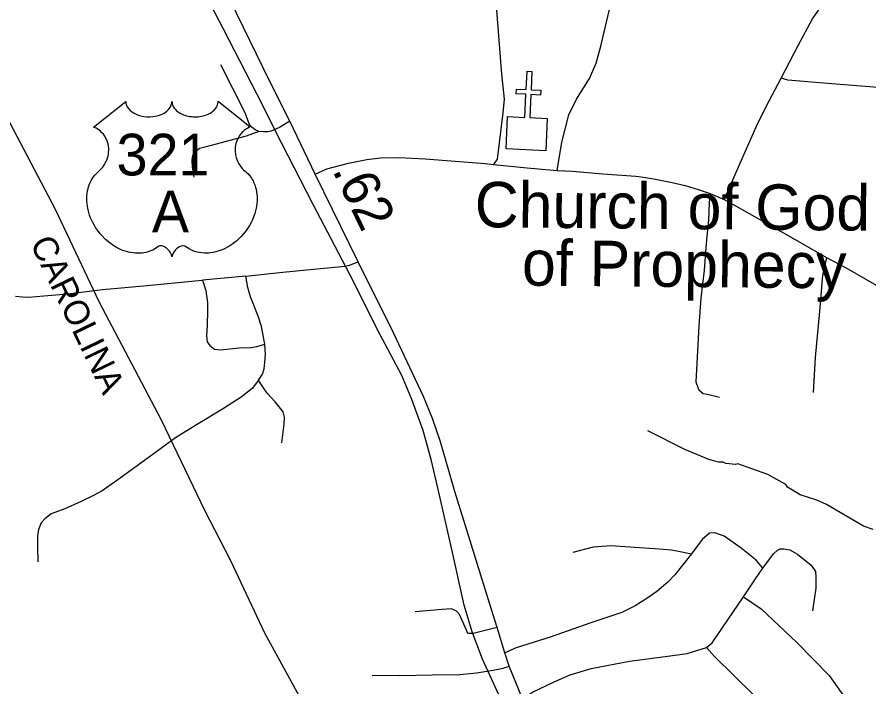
# Model space of a CAD drawing. Extents: x 1159738 to 1321356, y 736314 to 882035.
# Drawn here: x 1266042 to 1268853, y 761438 to 763648 of the extents above; entities that cross this region are included whole.
import ezdxf

# ---------------------------------------------------------------- set-up
doc = ezdxf.new("R2010")
doc.units = 0
for name, color, linetype in [('Exist Cultural Church CELL', 7, 'Continuous'), ('Exist Cultural Church Label', 7, 'Continuous'), ('Exist Hydrographic Misc Water Feature', 7, 'Continuous'), ('Exist Railroad Mainline', 7, 'Continuous'), ('Exist Railroad Mainline Label', 7, 'Continuous'), ('Exist Road Non-System Type 51', 7, 'Continuous'), ('Exist Road Primary US Attributed', 7, 'Continuous'), ('Exist Road Primary US Mileage Hundredths English Label', 7, 'Continuous'), ('Exist Road Primary US Shield CELL', 7, 'Continuous'), ('Exist Road Primary US Shield Number Label', 7, 'Continuous'), ('Exist Utilities Electrical Transmission Line', 7, 'Continuous')]:
    doc.layers.add(name, color=color, linetype=linetype)

msp = doc.modelspace()

# ---------------------------------------------------------------- linework, layer by layer
at = {"layer": 'Exist Cultural Church CELL'}
msp.add_lwpolyline([(1267660.9, 763319.4), (1267717.8, 763316.8), (1267721.4, 763392.9), (1267689.4, 763394.4), (1267690.2, 763410.3), (1267722.1, 763408.8), (1267725, 763468.9), (1267741, 763468.2), (1267738.2, 763408.1), (1267770.1, 763406.6), (1267769.4, 763390.6), (1267737.4, 763392.1), (1267733.8, 763316.1), (1267791.4, 763313.2), (1267786.4, 763206.9), (1267655.9, 763213)], close=True, dxfattribs=at)
at = {"layer": 'Exist Hydrographic Misc Water Feature'}
msp.add_lwpolyline([(1268866.3, 761957.4), (1268834.6, 761968.4), (1268712.6, 762039.8), (1268681, 762054.7), (1268625.5, 762072.3), (1268584.7, 762097.5), (1268578.4, 762105.7), (1268519.2, 762139.4), (1268420.2, 762174.2), (1268412.2, 762172.4), (1268380.2, 762175.4), (1268372.3, 762179.6), (1268356.4, 762180), (1268324.6, 762188.9), (1268245.5, 762221.2), (1268123.2, 762282.7)], dxfattribs=at)
at = {"layer": 'Exist Railroad Mainline'}
msp.add_lwpolyline([(1267632.3, 761412.3), (1267577.6, 761530.2), (1267544.4, 761620), (1267518, 761708.5), (1267474.8, 761901.5), (1267436.6, 762071.1), (1267410.2, 762184.1), (1267382, 762284.6), (1267345, 762386.7), (1267311.8, 762465.8), (1267239.1, 762602.1), (1267140, 762798.6), (1267019.6, 763029.2), (1266916.1, 763231.1), (1266834.7, 763392.2), (1266722.5, 763609.6), (1266667.4, 763716.8), (1266561.4, 763921.8), (1266492.4, 764059.9), (1266431, 764179.4), (1266408.5, 764222.6)], dxfattribs=at)
at = {"layer": 'Exist Road Non-System Type 51'}
for points in [[(1267824.7, 763141.4), (1267839.3, 763234.8), (1267863, 763325.7), (1267887.9, 763376.8), (1267931.5, 763445.4), (1267952.7, 763495.2), (1267968.9, 763551.3), (1268008.6, 763725.3), (1268029.8, 763852.5), (1268064.5, 764031.3), (1268078.2, 764066.2), (1268125.6, 764177.1), (1268150.4, 764204), (1268191.5, 764243.9), (1268225.1, 764295), (1268289.9, 764410.9)], [(1268563.8, 763446.1), (1268619.3, 763553.9), (1268666.8, 763642.2), (1268689.7, 763674.4), (1268713.5, 763702.3), (1268772.5, 763759.3), (1268836.7, 763812.6), (1268924.2, 763880.5), (1269025.3, 763956.6), (1269136.5, 764039.4), (1269295.8, 764161.1), (1269340.5, 764199.1), (1269364.1, 764225.4), (1269391.9, 764247.8), (1269429.9, 764278.4), (1269452.3, 764294), (1269510.6, 764327.3)], [(1267618, 763758.3), (1267626.7, 763642.4), (1267640.4, 763459.7), (1267649.1, 763377.4), (1267645.3, 763331.4), (1267626.7, 763179.4), (1267614.2, 763161.2)], [(1266942, 763304.8), (1266908.1, 763283.6), (1266893.4, 763277.2), (1266880.6, 763271.5), (1266869.7, 763269.5), (1266855.6, 763269.5), (1266840.3, 763270.8), (1266828.1, 763275.3), (1266817.9, 763283.6), (1266809.6, 763293.9), (1266793.6, 763333.6), (1266714.9, 763489.8)], [(1268375.3, 763045.7), (1268456.3, 763230.2), (1268486.2, 763297.9), (1268523.7, 763371.2), (1268563.8, 763446.1)], [(1269869.3, 763313.1), (1269805.5, 763337.6), (1269739.7, 763351.2), (1269587.8, 763361.3), (1269350.3, 763379.7), (1268882.1, 763415), (1268703.1, 763429.9), (1268585.5, 763439.4), (1268563.8, 763446.1)], [(1266840.3, 763270.8), (1266798.1, 763254.8), (1266662.4, 763218.3), (1266644.7, 763214.1), (1266631.3, 763203.2), (1266621.7, 763191.6), (1266619.1, 763176.3), (1266619.8, 763152.6), (1266626, 763120.2)], [(1267025.9, 763129.5), (1267064.3, 763147.4), (1267135.9, 763166), (1267196.7, 763178.4), (1267241.4, 763183.6), (1267303, 763184.3), (1267388.8, 763179.8), (1267586.4, 763164.5), (1267614.2, 763161.2), (1267725, 763150.3), (1267811.9, 763142.5), (1267824.7, 763141.4)], [(1267824.7, 763141.4), (1267875.1, 763139.1), (1267974.8, 763131), (1268083.4, 763122.8), (1268109.1, 763119.4), (1268149.2, 763112.6), (1268204.1, 763101.8), (1268246.9, 763092.3), (1268289.9, 763079.4), (1268328.6, 763065.8)], [(1268328.6, 763065.8), (1268325.9, 763036.1), (1268323.2, 762978.4), (1268317.8, 762924.8), (1268313.7, 762872.5), (1268309.6, 762813.4), (1268298.8, 762720.1), (1268292, 762629.8), (1268285.2, 762505.2), (1268281.8, 762444.8), (1268287.9, 762425.8), (1268292, 762418.3), (1268306.3, 762406.1), (1268320.4, 762404.3), (1268360.4, 762394.2)], [(1268328.6, 763065.8), (1268375.3, 763045.7)], [(1268375.3, 763045.7), (1268414.7, 763023.9), (1268493.4, 762979.8), (1268586.3, 762927.5), (1268712.5, 762854.9)], [(1268712.5, 762854.9), (1268699.6, 762795.6), (1268689.9, 762677.5), (1268675.8, 762524.7), (1268668.5, 762409.4)], [(1268712.5, 762854.9), (1268775.8, 762821.3), (1268876.2, 762763.6), (1268912.8, 762741.2), (1268955.6, 762709.9), (1268977.9, 762692.4), (1269003.7, 762666.6), (1269036.9, 762628.6), (1269064.1, 762597.4)], [(1266797.3, 762793.5), (1266908.7, 762805.8), (1267031.7, 762817.3), (1267124.4, 762826), (1267139.2, 762829.2), (1267167.6, 762840.9)], [(1266797.3, 762793.5), (1266654.6, 762780)], [(1266860.2, 762569.2), (1266849, 762627.1), (1266837.5, 762661), (1266813.1, 762725.1), (1266803.5, 762755.9), (1266797.3, 762793.5)], [(1266036.9, 762727.4), (1266060, 762724.8), (1266079.8, 762723.5), (1266130.4, 762728), (1266209.9, 762735.1), (1266324.6, 762749.2), (1266472.2, 762762.7), (1266628.5, 762777.4), (1266654.6, 762780)], [(1266654.6, 762780), (1266664.8, 762746.1), (1266671.2, 762705.7), (1266671.2, 762680.1), (1266669.2, 762630.1), (1266667.3, 762596.7), (1266669.2, 762576.2), (1266678.2, 762564), (1266693.6, 762551.9), (1266713.4, 762549.9), (1266775.6, 762556.3), (1266814, 762558.3), (1266833.9, 762560.8), (1266860.2, 762569.2)], [(1266839.5, 762450.3), (1266851.9, 762469.4), (1266857.3, 762487.2), (1266860.4, 762509), (1266861.9, 762534.6), (1266860.2, 762569.2)], [(1266839.5, 762450.3), (1266818.6, 762423.1), (1266781.4, 762393.6), (1266720.2, 762354.8), (1266634.9, 762302.8), (1266565.3, 762260.3), (1266474.6, 762193.6), (1266374.8, 762121), (1266323.7, 762085.3), (1266294.2, 762069.8), (1266253.9, 762049.7), (1266199.6, 762025.6), (1266155.4, 762009.3), (1266133.7, 761993), (1266122.2, 761979.2), (1266113.7, 761957.5), (1266109.8, 761936.6), (1266109.8, 761897.8), (1266111.4, 761851.2)], [(1266916.2, 762244), (1266924, 762305.3), (1266924.7, 762327.8), (1266920.1, 762345.6), (1266893.7, 762378.2), (1266868.1, 762406.9), (1266855.7, 762424.7), (1266844.9, 762441), (1266839.5, 762450.3)], [(1268502.3, 761830), (1268481, 761856.5), (1268431.7, 761896.2), (1268375.1, 761936), (1268344.9, 761946.3), (1268327.3, 761945.5), (1268302.3, 761924.9), (1268267.2, 761877.8)], [(1267876.9, 761883), (1267944.6, 761900.6), (1268001.9, 761905), (1268079.1, 761899.1), (1268146, 761894.7), (1268201.2, 761891.1), (1268229.9, 761885.2), (1268267.2, 761877.8)], [(1268502.3, 761830), (1268538.3, 761877.1), (1268550.8, 761889.6), (1268560.4, 761894), (1268572.1, 761894), (1268592, 761890.3), (1268617, 761876.4), (1268662.6, 761839.6), (1268676.5, 761819), (1268678, 761800.6), (1268677.3, 761763.8), (1268666.3, 761689.5)], [(1268267.2, 761877.8), (1268213, 761807.9), (1268189.4, 761783.6), (1268152.7, 761753.4), (1268123.3, 761732.1), (1268081.3, 761705.6), (1268038, 761684.3), (1267932.1, 761649), (1267804.3, 761603.6), (1267688.9, 761567.5), (1267652.1, 761551.3)], [(1268439.1, 761735.3), (1268478.8, 761794.7), (1268502.3, 761830)], [(1268316.8, 761568.7), (1268335.4, 761583.8), (1268439.1, 761735.3)], [(1268439.1, 761735.3), (1268497.2, 761696.3), (1268615.5, 761585.2), (1268722.2, 761476.3), (1268774.2, 761400.8), (1268809.5, 761369.2), (1268908.8, 761283.8)], [(1267626.9, 761634.6), (1267546.7, 761614.8), (1267529.1, 761614.8), (1267524.7, 761625.1), (1267501.9, 761677.3), (1267492.3, 761688.3), (1267475.4, 761696.4), (1267444.5, 761693.5), (1267355.6, 761686.1)], [(1267709.5, 761398.6), (1267742.6, 761420.7), (1267814.1, 761455.6), (1267867.6, 761478.1), (1267936.6, 761499.6), (1268062.8, 761523.4), (1268180.4, 761538.5), (1268253, 761549), (1268316.8, 761568.7)], [(1268316.8, 761568.7), (1268342.9, 761539.2), (1268471.6, 761411.9), (1268611.3, 761258.2), (1268628.9, 761233.1)], [(1267214.4, 761477.2), (1267305.6, 761476.4), (1267412.2, 761477.9), (1267503.4, 761479.4), (1267557.8, 761485.3), (1267612.9, 761493.3), (1267646, 761500.7), (1267665.9, 761506.6)]]:
    msp.add_lwpolyline(points, dxfattribs=at)
at = {"layer": 'Exist Road Primary US Attributed'}
msp.add_lwpolyline([(1267770.5, 761277.6), (1267723.5, 761365.7), (1267709.5, 761398.6), (1267665.9, 761506.6), (1267652.1, 761551.3), (1267626.9, 761634.6), (1267606.6, 761697.2), (1267486.8, 762082.8), (1267439.8, 762247.1), (1267412.9, 762323.2), (1267383.5, 762396.7), (1267284.5, 762606.7), (1267167.6, 762840.9), (1267025.9, 763129.5), (1266942, 763304.8), (1266875.5, 763437), (1266724.1, 763747.5), (1266572.6, 764058.7), (1266474.4, 764251.2)], dxfattribs=at)
at = {"layer": 'Exist Road Primary US Shield CELL'}
msp.add_lwpolyline([(1266401.3, 763369.5), (1266401.6, 763365.1), (1266402.7, 763359.9), (1266403.5, 763357.2), (1266406, 763352), (1266410, 763345.9), (1266415.6, 763340), (1266421.9, 763334.8), (1266426.2, 763332), (1266433.4, 763328.1), (1266441.7, 763324.6), (1266450.8, 763322), (1266460.2, 763320.1), (1266470.4, 763319), (1266480.5, 763318.8), (1266491.4, 763319.6), (1266503.5, 763321.9), (1266509.1, 763323.4), (1266515.3, 763325.5), (1266521.1, 763327.9), (1266527.4, 763331.3), (1266532.5, 763334.6), (1266536.5, 763337.5), (1266542.1, 763342.9), (1266546.6, 763348.4), (1266548.5, 763351.6), (1266550.1, 763354.6), (1266552.4, 763361), (1266553, 763363.8), (1266553.4, 763369.7), (1266553.8, 763364.8), (1266554.3, 763361.7), (1266555.1, 763358.7), (1266556.4, 763355.5), (1266558.6, 763351), (1266561.1, 763347.2), (1266565.9, 763341.6), (1266568.8, 763338.8), (1266571.5, 763336.6), (1266578.8, 763331.7), (1266587.2, 763327.4), (1266591.3, 763325.6), (1266595.6, 763324.1), (1266601, 763322.4), (1266606.6, 763321.1), (1266612.1, 763320.2), (1266617.8, 763319.4), (1266623.5, 763318.9), (1266628.2, 763318.8), (1266634, 763318.9), (1266639.4, 763319.2), (1266644.8, 763319.8), (1266650.8, 763320.8), (1266655.7, 763321.9), (1266662.1, 763323.6), (1266667.9, 763325.7), (1266672.9, 763327.8), (1266679.5, 763331.3), (1266684.9, 763334.6), (1266688.8, 763337.8), (1266693.4, 763342), (1266697.8, 763347.1), (1266700.4, 763350.8), (1266702.2, 763354.7), (1266703.9, 763358.7), (1266704.9, 763363), (1266705.4, 763366.7), (1266705.5, 763369.8), (1266811.8, 763285.2), (1266809.3, 763284.2), (1266803.5, 763281.4), (1266798.9, 763278.7), (1266791.6, 763273.5), (1266788.5, 763270.7), (1266785.4, 763267.7), (1266782.5, 763264.6), (1266779.9, 763261.7), (1266776.8, 763257.4), (1266774.1, 763253.1), (1266771.4, 763248.4), (1266769.4, 763244.3), (1266766.1, 763235.8), (1266764.6, 763230.4), (1266763.6, 763225.8), (1266762.3, 763216.3), (1266762, 763211.8), (1266762, 763207.3), (1266762.3, 763202.6), (1266762.7, 763198.1), (1266763.5, 763193.4), (1266764.3, 763189.3), (1266765.6, 763184.2), (1266767.5, 763178.3), (1266769.8, 763172.5), (1266774.6, 763163.3), (1266780.9, 763153.9), (1266785.3, 763148.6), (1266789.7, 763144.1), (1266796.3, 763138.6), (1266799.8, 763135.4), (1266803.9, 763131.3), (1266810.6, 763123.6), (1266813.3, 763120), (1266816, 763115.9), (1266818.5, 763111.7), (1266821, 763107.2), (1266823, 763103.2), (1266826.8, 763094.1), (1266829.5, 763085.3), (1266830.8, 763080.6), (1266832.7, 763070.2), (1266833.5, 763065), (1266834.3, 763054.9), (1266834.3, 763042.6), (1266833.4, 763030.9), (1266831.2, 763017.2), (1266829.4, 763009.1), (1266826.6, 762999.6), (1266823.9, 762991.4), (1266819, 762979.2), (1266814.7, 762970.5), (1266809.1, 762960.2), (1266805.3, 762953.9), (1266800.9, 762947.3), (1266795.3, 762939.6), (1266788.7, 762931.5), (1266780.9, 762922.9), (1266774.6, 762916.5), (1266766.3, 762909.1), (1266761.2, 762905), (1266754.1, 762899.6), (1266744.3, 762893), (1266734.6, 762887.4), (1266726.4, 762883.2), (1266719.1, 762880.1), (1266709.7, 762876.5), (1266694, 762872.2), (1266688.3, 762871), (1266681.5, 762870), (1266675.2, 762869.4), (1266669, 762869), (1266660.8, 762869), (1266652.5, 762869.6), (1266644.8, 762870.7), (1266636.7, 762872.4), (1266628.2, 762874.9), (1266620.5, 762878), (1266612.7, 762881.8), (1266599.6, 762890.1), (1266595.8, 762892.1), (1266593.6, 762892.6), (1266588.5, 762892.9), (1266583.8, 762891.9), (1266578.9, 762889.9), (1266575.9, 762888.4), (1266572, 762885.8), (1266569, 762883.4), (1266565.4, 762880), (1266562.8, 762877.1), (1266560.9, 762874.8), (1266557.2, 762869), (1266555.9, 762866.2), (1266554.5, 762862.6), (1266553.3, 762857.4), (1266551.6, 762864), (1266549.7, 762868.4), (1266547.4, 762872.2), (1266545.1, 762875.5), (1266541.4, 762879.8), (1266538.1, 762883), (1266534, 762886.2), (1266529.8, 762888.8), (1266526.3, 762890.6), (1266523.2, 762891.8), (1266519.4, 762892.7), (1266516.2, 762893), (1266513.7, 762892.9), (1266510.1, 762892.1), (1266505.3, 762888.6), (1266500.8, 762885.5), (1266495.8, 762882.4), (1266489.9, 762879.3), (1266485.6, 762877.3), (1266480.4, 762875.3), (1266474.4, 762873.2), (1266467.9, 762871.5), (1266461.2, 762870.2), (1266455.3, 762869.3), (1266448.9, 762868.7), (1266443.2, 762868.5), (1266437.2, 762868.6), (1266431.7, 762869), (1266425.2, 762869.6), (1266417.2, 762870.8), (1266410.5, 762872.3), (1266403.5, 762874.2), (1266396.3, 762876.4), (1266388.5, 762879.4), (1266378.9, 762883.6), (1266372.2, 762887.1), (1266361.6, 762893.2), (1266349.1, 762901.8), (1266339.7, 762909.4), (1266332.9, 762915.6), (1266322.8, 762925.9), (1266316.8, 762932.6), (1266307.5, 762944.6), (1266301.5, 762953.4), (1266297.7, 762959.8), (1266292, 762970.1), (1266288.9, 762976.5), (1266284.9, 762986), (1266281.7, 762994.6), (1266279.1, 763002.7), (1266277.7, 763007.9), (1266275.7, 763017.1), (1266274.5, 763023.5), (1266273.3, 763032.4), (1266272.6, 763041.7), (1266272.5, 763050.3), (1266272.7, 763057.5), (1266273.5, 763065.8), (1266274.9, 763074.7), (1266276.6, 763082.3), (1266278.2, 763087.8), (1266280.4, 763094.4), (1266283.4, 763101.8), (1266286.9, 763108.8), (1266290.3, 763114.6), (1266294.5, 763120.9), (1266298.6, 763126.3), (1266304.1, 763132.2), (1266309.7, 763137.6), (1266314.9, 763141.8), (1266321, 763147.8), (1266324.2, 763151.4), (1266328.1, 763156.5), (1266331.2, 763161.2), (1266333.6, 763165.4), (1266336.9, 763171.7), (1266338.8, 763176.3), (1266341.3, 763183.5), (1266342.5, 763188.5), (1266343.7, 763195), (1266344.5, 763201.1), (1266344.9, 763208.7), (1266344.7, 763214.9), (1266343.9, 763222.3), (1266342.5, 763229.3), (1266340.8, 763235.5), (1266338.2, 763242.5), (1266335.8, 763247.7), (1266331.7, 763254.6), (1266327.2, 763261.1), (1266322.5, 763266.4), (1266317.8, 763271.1), (1266313.3, 763274.6), (1266309, 763277.7), (1266303.6, 763280.9), (1266298.4, 763283.5), (1266295.1, 763284.8)], close=True, dxfattribs=at)
at = {"layer": 'Exist Utilities Electrical Transmission Line'}
msp.add_lwpolyline([(1264047.8, 766241.8), (1264134.6, 766107.9), (1264490.2, 765612), (1264597.9, 765419.3), (1264841.8, 765061.5), (1265032.3, 764772.7), (1265146.8, 764603.1), (1265286.3, 764407.9), (1265483.5, 764116), (1265742.9, 763726.6), (1265971.2, 763386.9), (1266167.7, 763013.6), (1266312.1, 762709.1), (1266518.3, 762319), (1266660.9, 762021.7), (1266746.6, 761855.9), (1266858.6, 761616.3), (1266991.6, 761373.6)], dxfattribs=at)

# ---------------------------------------------------------------- texts
at = {"layer": 'Exist Cultural Church Label'}
for s, p in [('Church of God', (1267551.8, 762954.8)), ('of Prophecy', (1267707.7, 762762.4))]:
    msp.add_text(s, height=150, rotation=359.4882, dxfattribs=at).set_placement(p)
at = {"layer": 'Exist Railroad Mainline Label'}
msp.add_text('CAROLINA', height=82.02, rotation=295.7047, dxfattribs=at).set_placement((1266084, 762902.4))
at = {"layer": 'Exist Road Primary US Mileage Hundredths English Label'}
msp.add_text('.62', height=125, rotation=295.8758, dxfattribs=at).set_placement((1267081.1, 763142.8))
at = {"layer": 'Exist Road Primary US Shield Number Label'}
for s, p in [('321', (1266370.7, 763125.4)), ('A', (1266487.2, 762937.5))]:
    msp.add_text(s, height=137.5, dxfattribs=at).set_placement(p)

doc.saveas('drawing.dxf')
